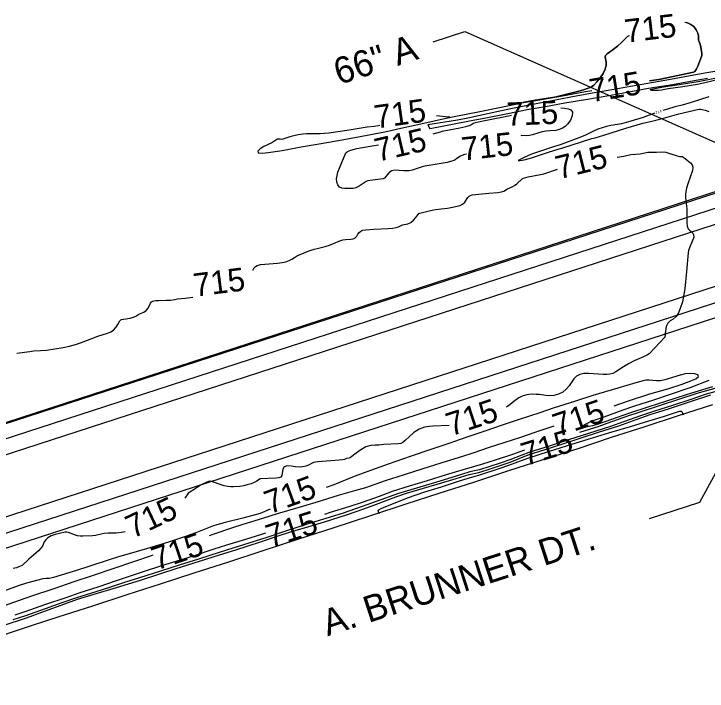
# Model space of a CAD drawing. Extents: x -468563856 to 36492962, y -306094093 to 11899197.
# Drawn here: x 1825949 to 1826935, y 532272 to 533234 of the extents above; entities that cross this region are included whole.
import ezdxf

# ---------------------------------------------------------------- set-up
doc = ezdxf.new("R2010")
doc.units = 0
for name, color, linetype in [('Default', 7, 'Continuous'), ('DT_X_Contour_Minor', 7, 'Continuous'), ('Level 14', 7, 'Continuous'), ('Level 19', 7, 'Continuous'), ('Level 40', 7, 'Continuous'), ('SC_Shading3', 7, 'Continuous')]:
    doc.layers.add(name, color=color, linetype=linetype)

msp = doc.modelspace()

# ---------------------------------------------------------------- linework, layer by layer
at = {"layer": 'Default'}
for points in [[(1824453.94, 532169.95), (1824460.14, 532150.86), (1827123.3, 533015.47), (1827116.51, 533036.4)], [(1824499.66, 532029.12), (1824505.86, 532010.03), (1827169.02, 532874.64), (1827162.83, 532893.73)]]:
    msp.add_lwpolyline(points, close=True, dxfattribs=at)
at = {"layer": 'DT_X_Contour_Minor'}
for points in [[(1826903.1, 533222.15), (1826906.83, 533221.17), (1826911.64, 533219.18), (1826916.13, 533216.02), (1826919.41, 533211.6), (1826921.48, 533206.75), (1826922.52, 533202.52), (1826922.71, 533196.91), (1826923.16, 533195.81), (1826925, 533191.26), (1826926.03, 533186.94), (1826927.42, 533177.98), (1826927.46, 533175.41), (1826926.93, 533173.37), (1826921.57, 533159.97), (1826919.29, 533155.16), (1826917.32, 533152.34), (1826915.73, 533151.15), (1826895.46, 533146.93), (1826866.38, 533141.04), (1826852.75, 533138.77)], [(1826853.39, 533138.88), (1826866.38, 533141.04), (1826895.46, 533146.93), (1826915.73, 533151.15), (1826917.32, 533152.34), (1826919.29, 533155.16), (1826921.57, 533159.97), (1826926.93, 533173.37), (1826927.46, 533175.41), (1826927.42, 533177.98), (1826926.03, 533186.94), (1826925, 533191.26), (1826923.16, 533195.81), (1826922.71, 533196.91), (1826922.52, 533202.52), (1826921.48, 533206.75), (1826919.41, 533211.6), (1826916.13, 533216.02), (1826911.64, 533219.18), (1826906.83, 533221.17), (1826905.76, 533221.45)], [(1826824.33, 533203.13), (1826822.41, 533202.38), (1826813.13, 533193.23), (1826807.34, 533188.31), (1826801.44, 533183.67), (1826792.63, 533177.31), (1826790.51, 533174.94), (1826790.15, 533172.55), (1826791.45, 533166.09), (1826791.29, 533161.37), (1826789.94, 533155.76), (1826787.15, 533149.55), (1826782.91, 533143.15), (1826778.08, 533137.3), (1826773.74, 533132.89), (1826770.68, 533130.45), (1826768.54, 533129.38), (1826764.39, 533127.84), (1826760.69, 533126.43), (1826754.57, 533124.52), (1826735.68, 533119.8), (1826718.41, 533115.95), (1826690.58, 533111.27), (1826672.73, 533108.3), (1826690.58, 533111.27), (1826718.41, 533115.95), (1826735.68, 533119.8)], [(1826735.68, 533119.8), (1826754.57, 533124.52), (1826760.69, 533126.43), (1826764.39, 533127.84), (1826768.54, 533129.38), (1826770.68, 533130.45), (1826773.74, 533132.89), (1826778.08, 533137.3), (1826782.91, 533143.15), (1826787.15, 533149.55), (1826789.94, 533155.76), (1826791.29, 533161.37), (1826791.45, 533166.09), (1826790.15, 533172.55), (1826790.51, 533174.94), (1826792.63, 533177.31), (1826801.44, 533183.67), (1826807.34, 533188.31), (1826813.13, 533193.23), (1826822.41, 533202.38), (1826823.82, 533202.93)], [(1826960.15, 533154.66), (1826931.61, 533149.8), (1826908.42, 533145.68), (1826882.92, 533141.07), (1826858.46, 533136.46), (1826825.78, 533130.78), (1826799.88, 533126.29), (1826769.03, 533120.9), (1826741.37, 533115.58), (1826711.71, 533109.98), (1826679.66, 533104.12), (1826653.42, 533098.69), (1826625.22, 533092.65), (1826594.73, 533085.88), (1826579.86, 533082.81), (1826537.94, 533076.4), (1826540.79, 533071.39), (1826543.69, 533071.78), (1826560.37, 533074.95), (1826594.67, 533081.46), (1826622.49, 533086.68), (1826649.2, 533091.89), (1826681.61, 533098.49), (1826705.17, 533102.59), (1826732.64, 533107.48), (1826764.63, 533112.92), (1826795.02, 533118.17), (1826821.29, 533122.85), (1826851.42, 533128.4), (1826885.55, 533133.96), (1826911.36, 533138.24), (1826935.28, 533142.74)], [(1826945.21, 533139.22), (1826929.93, 533135.52), (1826921.1, 533133.78), (1826900.32, 533130.53), (1826879.44, 533127.4), (1826869.92, 533125.54), (1826865.94, 533125.19), (1826860.79, 533125.12), (1826856.12, 533125.36), (1826854.07, 533125.98), (1826856.03, 533126.96), (1826865.35, 533129.08), (1826873.02, 533130.45), (1826901.3, 533134.61), (1826922.3, 533137.83), (1826945.75, 533142.86), (1826952.34, 533144.08), (1826952.43, 533143.6), (1826952.13, 533142.65), (1826951.64, 533141.97), (1826950.7, 533141.24), (1826947.63, 533139.97), (1826945.21, 533139.22)], [(1826469.85, 533075.54), (1826467.88, 533074.89), (1826461.53, 533073.92), (1826451.67, 533073), (1826426.15, 533068.67), (1826397.01, 533064.7), (1826385.02, 533063.58), (1826375.34, 533063.49), (1826365.56, 533063.49), (1826359.95, 533063.07), (1826353.68, 533062.17), (1826347.29, 533060.87), (1826341.45, 533059.33), (1826330.25, 533055.74), (1826328.09, 533055.89), (1826326.21, 533056.27), (1826324.22, 533056.1), (1826321.8, 533054.84), (1826315.94, 533050.97), (1826304.6, 533045.67), (1826299.64, 533042.37), (1826296.1, 533038.9), (1826296.44, 533036.51), (1826302.13, 533036.04), (1826310.89, 533036.91), (1826330.65, 533040.04), (1826357.78, 533044.94), (1826386.02, 533049.92), (1826416.04, 533055), (1826444.22, 533060.23), (1826476.89, 533066.48), (1826503.89, 533072.43), (1826532.02, 533078.61), (1826561.71, 533085.21), (1826577.51, 533088.55), (1826611.89, 533095.47), (1826639.79, 533101.14), (1826673.8, 533108), (1826702.32, 533112.76), (1826729.09, 533117.41), (1826762.09, 533123.71), (1826771.01, 533125.29)], [(1826937.2, 533115.99), (1826912.13, 533108.04), (1826899.48, 533104.37), (1826888.81, 533101.79), (1826878.49, 533098.72), (1826872.12, 533096.7)], [(1826860.72, 533092.97), (1826852.62, 533090.05), (1826844.07, 533086.81), (1826826.6, 533081.47), (1826813.33, 533077.9), (1826807.29, 533076.95), (1826797.9, 533075.32), (1826791.89, 533073.92), (1826785.58, 533072.14), (1826779.57, 533070.11), (1826774.5, 533068.05), (1826761.06, 533061.17), (1826752.72, 533057.81), (1826726.08, 533048.03), (1826716.28, 533045.09), (1826693.69, 533037.64), (1826685.21, 533034.52), (1826674.7, 533030.01), (1826668.94, 533027.29), (1826666.41, 533025.54), (1826669.03, 533025.5), (1826674.84, 533026.64), (1826685.1, 533029.34), (1826709.55, 533037.75), (1826724.69, 533042.49), (1826730, 533043.78), (1826743.21, 533047.98), (1826770.99, 533057.03), (1826775.68, 533058.09), (1826788.09, 533061.85), (1826819.14, 533071.81), (1826843.61, 533078.73), (1826854.39, 533081.37), (1826864.06, 533083.49), (1826878.12, 533087.36), (1826894.55, 533091.88), (1826923, 533098.55), (1826925.3, 533098.7), (1826927.95, 533098.22), (1826932.12, 533097.13), (1826937.11, 533095.56)], [(1826726.94, 533100.77), (1826732.29, 533100.24), (1826737.42, 533099.34), (1826741.38, 533097.56), (1826743.38, 533094.28), (1826742.89, 533089.16), (1826740.5, 533083.23), (1826737.05, 533077.84), (1826733.28, 533074.03), (1826729.53, 533071.62), (1826726.05, 533070.12), (1826722.93, 533069.1), (1826719.76, 533068.41), (1826711.32, 533067.68), (1826706.01, 533067.27), (1826700.6, 533066.45), (1826695.51, 533065.05), (1826686.46, 533062.04), (1826682.44, 533061.27), (1826678.64, 533061.01), (1826671.14, 533061.08), (1826669.9, 533060.97)], [(1826545.46, 533063.47), (1826555.72, 533066.47), (1826558.17, 533067.41), (1826560.5, 533067.96), (1826583.54, 533072.07), (1826591.99, 533073.88), (1826597.15, 533075.53), (1826599.87, 533076.97), (1826601.67, 533078.21), (1826603.94, 533079.28), (1826607.58, 533080.36), (1826621.46, 533083.28), (1826652.64, 533089.3), (1826656.87, 533090.17)], [(1826550.11, 533089.6), (1826567.23, 533087.59), (1826569.03, 533087.22), (1826567.23, 533087.59)], [(1826592.91, 533034.64), (1826592.55, 533034.6), (1826588.59, 533033.8), (1826584.35, 533031.94), (1826580.36, 533029.51), (1826575.37, 533025.94), (1826573.59, 533025.09), (1826565.21, 533023.01), (1826551.05, 533020.29), (1826533.68, 533017.86), (1826530.03, 533016.91), (1826519.78, 533013.23), (1826515.44, 533012.06), (1826511.12, 533011.22), (1826507.13, 533010.86), (1826503.32, 533010.95), (1826490.86, 533012.17), (1826486.74, 533011.17), (1826483.1, 533008.58), (1826480.1, 533005.24), (1826476.28, 533000.54), (1826474.54, 532999.74), (1826466.68, 532998.74), (1826456, 532997.45), (1826452.71, 532996.86), (1826450.42, 532995.99), (1826440.08, 532989.19), (1826435.73, 532987.03), (1826431.79, 532986.1), (1826424.17, 532986.15), (1826419.89, 532986.15), (1826415.67, 532986.49), (1826412.13, 532987.92), (1826409.75, 532990.93), (1826408.51, 532995.12), (1826408.24, 532999.83), (1826408.77, 533004.54), (1826409.89, 533009.07), (1826413, 533017.41), (1826421.36, 533036.79), (1826423.6, 533038.69), (1826428.55, 533040.56), (1826437.02, 533042.6), (1826455.64, 533046.14), (1826467.5, 533047.94)], [(1826806.79, 533030.64), (1826816.61, 533031.69), (1826826.57, 533034.03), (1826839.67, 533035), (1826850.59, 533037.53), (1826854.43, 533037.77), (1826862.7, 533037.74), (1826871.29, 533038.02), (1826876.23, 533037.4), (1826881.82, 533035.79), (1826892.26, 533032.13), (1826895.71, 533031.45), (1826899.69, 533031.25), (1826901.07, 533030.67), (1826903.62, 533028.52), (1826906.64, 533025.99), (1826911.33, 533022.41), (1826913.65, 533019.74), (1826914.78, 533016.13), (1826914.09, 533011.41), (1826907.48, 532992.79), (1826905.76, 532986.57), (1826904.15, 532978.25), (1826904.17, 532973.58), (1826904.53, 532968.25), (1826905.88, 532956.97), (1826906.27, 532950.11), (1826905.97, 532937.15), (1826906.38, 532932.2), (1826907.83, 532928.8), (1826909.99, 532926.51), (1826912.37, 532924.67), (1826914.47, 532922.65), (1826915.77, 532920.04), (1826915.81, 532916.48), (1826914.31, 532911.79), (1826909.83, 532901.79), (1826908.52, 532897.89), (1826907.9, 532894.44), (1826905.66, 532868.11), (1826903.38, 532843.17), (1826899.87, 532824.8), (1826896.76, 532815.5), (1826894.12, 532809.28), (1826890.66, 532803.86), (1826886.53, 532800.45), (1826882.36, 532797.95), (1826878.93, 532794.72), (1826876.8, 532789.66), (1826875.72, 532783.86), (1826874.72, 532774.76), (1826860.4, 532759.31), (1826852.35, 532751.06), (1826850.18, 532749.47), (1826844.33, 532746.86), (1826830.96, 532740.9), (1826823.19, 532736.93), (1826816.13, 532732.71), (1826804.92, 532725.41), (1826800.71, 532723.19), (1826796.81, 532721.96), (1826792.51, 532721.53), (1826787.24, 532721.68), (1826766.91, 532723.16), (1826759.86, 532722.97), (1826753.75, 532721.73), (1826749.08, 532719.11), (1826745.43, 532715.31), (1826738.75, 532705.58), (1826734.71, 532700.62), (1826729.68, 532696.45), (1826723.48, 532693.57), (1826716.81, 532691.95), (1826710.58, 532691.37), (1826705.44, 532691.61), (1826696.55, 532692.98), (1826691.65, 532693.37), (1826686.49, 532693.39), (1826681.44, 532693.06), (1826676.75, 532692.33), (1826672.17, 532690.92), (1826667.33, 532688.47), (1826662.04, 532684.86), (1826653.08, 532677.63), (1826649.87, 532675)], [(1826289.08, 532869.82), (1826290.89, 532873.32), (1826292.88, 532875.26), (1826295.16, 532876.41), (1826299.75, 532877.68), (1826306.22, 532878.59), (1826324.35, 532880.03), (1826330.56, 532880.79), (1826336.12, 532881.87), (1826340.8, 532883.37), (1826344.58, 532885.39), (1826348.24, 532887.81), (1826352.76, 532890.49), (1826358.72, 532893.25), (1826370.25, 532897.67), (1826375.26, 532899.19), (1826376.18, 532899.52), (1826380.32, 532900.65), (1826391.79, 532903.37), (1826398.25, 532905.35), (1826403.82, 532907.65), (1826412.85, 532911.76), (1826416.96, 532912.87), (1826420.94, 532913.39), (1826428.52, 532913.86), (1826431.88, 532914.47), (1826434.65, 532915.85), (1826436.7, 532918.2), (1826438.43, 532921.02), (1826440.31, 532923.6), (1826442.71, 532925.41), (1826445.34, 532926.5), (1826449.81, 532927.4), (1826460.92, 532927.91), (1826481.57, 532928.94), (1826487.76, 532929.5), (1826492.72, 532930.38), (1826496.17, 532931.64), (1826498.83, 532933.03), (1826501.66, 532934.2), (1826509.59, 532935.92), (1826513.84, 532937.73), (1826517.6, 532940.85), (1826520.67, 532944.49), (1826524.95, 532950.22), (1826526.47, 532950.67), (1826541.6, 532954.43), (1826548.8, 532955.86), (1826561.06, 532957.39), (1826565.76, 532957.95), (1826572.69, 532959.48), (1826583.69, 532961.79), (1826587.34, 532963.58), (1826590.33, 532966.54), (1826594.81, 532973.08), (1826596.69, 532975.07), (1826598.35, 532976.14), (1826600.85, 532976.93), (1826605.62, 532977.51), (1826624.5, 532979.3), (1826637.5, 532980.21), (1826642.42, 532981.03), (1826645.89, 532982.35), (1826651.04, 532985.5), (1826657.53, 532988.19), (1826661.1, 532990.1), (1826664.52, 532992.79), (1826671.73, 532999.74), (1826673.69, 533000.71), (1826680.57, 533002.45), (1826697.79, 533005.67), (1826702.63, 533007), (1826722.36, 533013.63)], [(1825953.78, 532751.82), (1825971.91, 532754.19), (1825974.53, 532754.84), (1825977.66, 532755.32), (1825987.35, 532755.71), (1825995.6, 532756.18), (1826019.2, 532760.16), (1826028.54, 532761.95), (1826036.75, 532764.07), (1826045.6, 532767.14), (1826068.86, 532775.83), (1826076.44, 532778.23), (1826081.17, 532779.64), (1826086.17, 532781.61), (1826090.77, 532784.49), (1826094.42, 532788.41), (1826097.09, 532792.59), (1826100.09, 532797.92), (1826101.5, 532799.24), (1826102.58, 532799.65), (1826105.14, 532800.2), (1826114.84, 532801.78), (1826119.49, 532802.94), (1826122.53, 532804.39), (1826126.95, 532807.47), (1826134.02, 532810.39), (1826137.51, 532812.7), (1826140.1, 532816.03), (1826143.55, 532822.82), (1826145.13, 532824.71), (1826146.66, 532825.62), (1826151.11, 532826.78), (1826155.55, 532826.91), (1826166.5, 532827.04), (1826171.82, 532827.28), (1826178.38, 532828.3), (1826181.82, 532828.94), (1826192.89, 532830.22), (1826203.73, 532831.53)], [(1826802.59, 532677.06), (1826823.25, 532684.02), (1826853.64, 532693.87), (1826878.85, 532701.42), (1826899.36, 532707.8), (1826911.88, 532712.43), (1826918.63, 532715.51), (1826922.57, 532718.53), (1826921.87, 532721.03), (1826917.46, 532722.69), (1826911, 532723.2), (1826903.87, 532722.38), (1826896.52, 532720.58), (1826874.91, 532713.86), (1826868.48, 532712.7), (1826862.7, 532712.65), (1826852.58, 532713.58), (1826847.95, 532713.31), (1826843.76, 532712.54), (1826833.78, 532709.75), (1826807.97, 532702.23), (1826772.41, 532691.56), (1826747.58, 532683.86), (1826716.13, 532673.74), (1826696.97, 532667.33), (1826667.75, 532657.5), (1826643.55, 532649.41), (1826619.12, 532641.13), (1826592.09, 532631.82), (1826567.73, 532623.58), (1826540.54, 532614.55), (1826514.28, 532605.33), (1826481.56, 532594), (1826451.03, 532583.44), (1826433.24, 532576.42), (1826404.17, 532564.82), (1826393.27, 532560.88)], [(1826942.74, 532703.97), (1826912.52, 532695.27), (1826903.76, 532692.42), (1826875.83, 532683.09), (1826852.19, 532675.43), (1826823.2, 532666.09), (1826799.17, 532657.51), (1826778.76, 532650.43), (1826771.81, 532648.52), (1826765.39, 532647.37), (1826757.15, 532646.54), (1826756.1, 532646.82), (1826756.76, 532647.67), (1826761.25, 532650.36), (1826766.65, 532653.25), (1826773.06, 532656.05), (1826788.46, 532661.63), (1826815.71, 532671.45), (1826830.54, 532676.49), (1826859.16, 532685.71), (1826882.98, 532693.53), (1826910.75, 532702.93), (1826937.89, 532713.39)], [(1826952.94, 532698.98), (1826933.72, 532693.44), (1826911.71, 532686.28), (1826885.75, 532677.68), (1826860.14, 532669.42), (1826841.44, 532663.22), (1826815.89, 532654.16), (1826797.67, 532647.85), (1826766.03, 532637.71), (1826737.86, 532628.67), (1826711.65, 532620.39), (1826681.55, 532610.61), (1826671.38, 532606.9), (1826654.34, 532600.21), (1826640.53, 532595.53), (1826611.53, 532586.23), (1826604.11, 532584.58), (1826597.33, 532583.06), (1826585.66, 532579.54), (1826559.7, 532571.41), (1826539.47, 532565.31), (1826508.88, 532556.43), (1826496.25, 532552.28), (1826464.33, 532541.04), (1826444.71, 532534.09), (1826415.85, 532524.26), (1826392.72, 532517.02), (1826367.55, 532509.11), (1826338.27, 532499.76), (1826310.19, 532490.44), (1826290.74, 532484.18), (1826268.1, 532477.15), (1826242.64, 532469.2), (1826211.96, 532459.33), (1826184.33, 532450.45), (1826157.95, 532442.22), (1826127.87, 532432.48), (1826108.09, 532426.24), (1826085.35, 532419.07), (1826065.92, 532412.85), (1826038.4, 532404.34), (1826017.36, 532396.9), (1825993.89, 532388.61), (1825966.07, 532378.76), (1825947.74, 532372.72)], [(1826753.91, 532639.67), (1826781.36, 532648.37), (1826792.89, 532652.23), (1826823.51, 532663.09), (1826835.4, 532667.14), (1826867.31, 532677.42), (1826895.88, 532686.86), (1826920.78, 532694.96), (1826949.7, 532703.33)], [(1825934.22, 532364.86), (1825967.51, 532375.95), (1825998.05, 532386.92), (1826016.7, 532393.82), (1826040.02, 532402.17), (1826063.51, 532409.21), (1826095.48, 532418.92), (1826129.5, 532429.44), (1826157.01, 532438.36), (1826180.26, 532445.73), (1826213.25, 532456.16), (1826241.65, 532465.22), (1826265.05, 532472.59), (1826298.72, 532483.28), (1826326.4, 532492.59), (1826342.62, 532497.84), (1826367.33, 532505.11), (1826390.96, 532512.3), (1826422.32, 532522.05), (1826446.95, 532530.64), (1826465.1, 532537.27), (1826492.34, 532547.77), (1826507.7, 532553.06), (1826531.69, 532559.88), (1826551.12, 532565.49), (1826577.93, 532573.93), (1826596.58, 532579.67), (1826610.31, 532582.3), (1826627.93, 532587.83), (1826655.08, 532597.07), (1826680.26, 532607.18), (1826704.56, 532615.03), (1826728.58, 532622.72), (1826755.88, 532631.55), (1826780.49, 532639.42), (1826809.57, 532648.8), (1826835.22, 532657.96), (1826854.14, 532664.63), (1826879.79, 532672.89), (1826912.62, 532683.66), (1826940.41, 532692.79)], [(1826468.91, 532523.4), (1826467.7, 532526.41), (1826467.41, 532527.94), (1826468.4, 532529.4), (1826471.72, 532531.33), (1826477.97, 532534.08), (1826498.52, 532542.22), (1826508.97, 532546.11), (1826533.57, 532554.62), (1826557.31, 532562.13), (1826580.18, 532569.48), (1826595.31, 532574.27), (1826610.12, 532578.41), (1826640.54, 532588.43), (1826652.9, 532592.69), (1826665.58, 532597.62), (1826679.99, 532602.61), (1826711, 532612.65), (1826742.36, 532622.44), (1826765.87, 532629.82), (1826796.38, 532639.19), (1826825.85, 532647.79), (1826845.67, 532653.7), (1826874.09, 532662.59), (1826891.6, 532668.02), (1826896.32, 532669.4), (1826897.73, 532669.65), (1826898.59, 532669.53), (1826899.11, 532668.87), (1826900.31, 532665.48), (1826900.88, 532664.34)], [(1826568.08, 532649.08), (1826545.11, 532648.15), (1826539.74, 532647.82), (1826532.91, 532646.65), (1826525.42, 532643.82), (1826518.06, 532638.92), (1826511.44, 532633.16), (1826506.12, 532628.14), (1826502.38, 532625.09), (1826499.27, 532623.67), (1826495.54, 532623.12), (1826475.44, 532621.87), (1826472.21, 532621.45), (1826468.4, 532621.22), (1826463.12, 532621.16), (1826456.66, 532620.57), (1826449.57, 532618.58), (1826442.45, 532614.7), (1826436, 532610.01), (1826427.78, 532603.72), (1826426.03, 532602.89), (1826422.13, 532602.31), (1826419.26, 532600.98), (1826416.36, 532600.24), (1826411.93, 532599.64), (1826399.8, 532598.68), (1826381.58, 532597.34), (1826378.01, 532596.91), (1826375.54, 532596.34), (1826373.41, 532595.44), (1826368.01, 532592.61), (1826364.37, 532591.23), (1826359.99, 532590.26), (1826354.93, 532589.87), (1826349.31, 532590.17), (1826343.35, 532591.07), (1826337.87, 532591.57), (1826333.78, 532590.46), (1826331.69, 532586.99), (1826330.23, 532578.12), (1826328.85, 532575.61), (1826326.26, 532574.52), (1826322.09, 532574.19), (1826299.84, 532573.53), (1826298.59, 532572.79), (1826294.53, 532569.9), (1826291.07, 532568.1), (1826286.46, 532566.32), (1826281.15, 532564.72), (1826275.74, 532563.43), (1826270.72, 532562.55), (1826261.81, 532561.76), (1826257.69, 532561.75), (1826253.35, 532562.19), (1826248.37, 532563.36), (1826231.69, 532569.22), (1826228.35, 532569.76), (1826226.09, 532569.4), (1826218.39, 532566.18), (1826214.56, 532564.16), (1826205.76, 532558.33), (1826199.48, 532554.3), (1826197.04, 532552.93), (1826195.71, 532550.72), (1826194.43, 532548.67), (1826192.31, 532545.9)], [(1826227.24, 532492.71), (1826232.5, 532494.57), (1826259.38, 532503.73), (1826275.33, 532508.87), (1826303.49, 532517.53), (1826324.34, 532523.91), (1826353.69, 532532.57), (1826379.09, 532540.25), (1826410.71, 532549.95), (1826434.14, 532556.6), (1826449.49, 532561.21), (1826477.64, 532570.77), (1826504.7, 532579.58), (1826529.99, 532587.61), (1826558.27, 532596.31), (1826587.78, 532605.41), (1826602.19, 532610.29), (1826625.37, 532618.31), (1826646.48, 532624.97), (1826669.86, 532632.41), (1826690.6, 532639.45), (1826717.28, 532648.54)], [(1826391.25, 532523.18), (1826399.69, 532525.84), (1826427.37, 532534.48), (1826446.54, 532540.73), (1826468.94, 532548.88), (1826487.76, 532555.63), (1826511.59, 532563.3), (1826537.2, 532571.11), (1826564.44, 532579.36), (1826590.12, 532587.21), (1826612.58, 532593.73), (1826615.87, 532594.66), (1826634.25, 532600.53), (1826658.56, 532608.41), (1826675.76, 532614.51)], [(1826313.68, 532530.28), (1826299.34, 532524.07), (1826275.05, 532517.35), (1826249.5, 532511.15), (1826237.82, 532508.15), (1826231.83, 532506.09), (1826208.07, 532496.46), (1826193.22, 532491.23), (1826169.01, 532483.46), (1826142.48, 532475.18), (1826124.85, 532469.86), (1826096.46, 532462.08), (1826084.86, 532458.41), (1826057.39, 532449.29), (1826038.27, 532443.08), (1826005.84, 532433.11), (1826002.05, 532432.05), (1825999.61, 532431.64), (1825995.1, 532431.68), (1825990.56, 532431.02), (1825983.37, 532429.31), (1825967.32, 532424.82), (1825956.65, 532421.48), (1825927.81, 532411.43)], [(1826107.71, 532498.11), (1826105.32, 532497.58), (1826098.61, 532496.47), (1826094.5, 532496.23), (1826083.19, 532496.14), (1826077.67, 532495.75), (1826073.25, 532494.84), (1826065.52, 532492.69), (1826060.9, 532492.12), (1826047.33, 532491.58), (1826043.67, 532491.67), (1826039.8, 532492.35), (1826035.37, 532493.8), (1826027.2, 532496.99), (1826024.63, 532497.61), (1826022.32, 532497.49), (1826013.99, 532495.71), (1826007.99, 532494.2), (1826002.27, 532492.18), (1825997.83, 532489.65), (1825994.68, 532486.77), (1825992.57, 532483.76), (1825989.83, 532477.76), (1825987.74, 532474.59), (1825984.34, 532471.18), (1825970.49, 532459.24), (1825961.05, 532450), (1825956.56, 532448.15), (1825952.91, 532446.91), (1825948.35, 532445.78)], [(1825951.02, 532380.03), (1825965.55, 532384.93), (1825994.58, 532394.97), (1826023.57, 532404.83), (1826042.31, 532411.04), (1826070.74, 532420.14), (1826093.72, 532428.13), (1826112.51, 532434.55), (1826135.24, 532442), (1826159.85, 532449.94), (1826186.44, 532458.03), (1826203.14, 532463.36), (1826234.17, 532473.84), (1826252.31, 532479.52), (1826279.02, 532487.75), (1826301.82, 532494.63), (1826307.73, 532496.47)], [(1825633.35, 532297.1), (1825643.73, 532300.76), (1825664.21, 532307.87), (1825689.9, 532316.37), (1825716.86, 532325.09), (1825744.71, 532333.68), (1825769.66, 532341.36), (1825799.17, 532350.72), (1825824.66, 532359.31), (1825851.14, 532368.1), (1825882.89, 532378.55), (1825891.77, 532380.98), (1825913.53, 532385.79), (1825926.08, 532389.98), (1825957.55, 532401.06), (1825976.07, 532407.39), (1826006.61, 532417.37), (1826035.14, 532427.2), (1826061.35, 532436.03), (1826091.96, 532446.5), (1826119.9, 532455.99), (1826145.12, 532464.36), (1826147.37, 532465.1)]]:
    msp.add_lwpolyline(points, dxfattribs=at)
at = {"layer": 'Level 14'}
msp.add_lwpolyline([(1826942.48, 532678.66), (1826893.93, 532662.86), (1826846.15, 532647.38), (1826798.64, 532631.9), (1826750.96, 532616.13), (1826701.17, 532600.31), (1826652.53, 532584.6), (1826604.08, 532568.59), (1826553.59, 532552.39), (1826506.81, 532537.17), (1826456.45, 532520.69), (1826404.38, 532503.88), (1826352.49, 532487.03), (1826303.17, 532471.02), (1826254.47, 532455.03), (1826205.13, 532439.16), (1826157.18, 532423.69), (1826110.15, 532408.48), (1826061.29, 532392.41), (1826011.75, 532376.55), (1825975.31, 532364.63), (1825922.34, 532347.34)], dxfattribs=at)
at = {"layer": 'Level 40'}
for p, q in [((1826545.25, 533194.52), (1826590.65, 533209.25)), ((1826590.65, 533209.25), (1827056.56, 533002.67))]:
    msp.add_line(p, q, dxfattribs=at)
msp.add_lwpolyline([(1827043.56, 532758.31), (1826923.88, 532539.43), (1826852.55, 532516.27)], dxfattribs=at)
at = {"layer": 'SC_Shading3'}
for points in [[(1824466.95, 532129.88), (1824453.94, 532169.95), (1827117.12, 533034.5), (1827130.09, 532994.55)], [(1824492.87, 532050.04), (1824505.84, 532010.09), (1827169, 532874.71), (1827156.03, 532914.66)]]:
    msp.add_lwpolyline(points, close=True, dxfattribs=at)

# ---------------------------------------------------------------- texts
at = {"layer": 'Level 19'}
for s, height, rotation, p in [('715', 33, 6.78382, (1826819.51, 533193.08)), ('715', 33, 9.27619, (1826770.34, 533108.53)), ('715', 33, 8.01568, (1826464.04, 533071.01)), ('715', 33, 2.41788, (1826650.21, 533075.01)), ('714', 4, 17.62418, (1826862.04, 533091.4)), ('715', 33, 13.09781, (1826466.54, 533023.75)), ('715', 33, 6.27389, (1826587.37, 533025.59)), ('715', 33, 14.11195, (1826724.17, 532998.74)), ('715', 33, 7.32813, (1826206.65, 532831.97)), ('715', 33, 18.35184, (1826570.49, 532633.58)), ('715', 33, 18.4607, (1826722.19, 532632.59)), ('715', 33, 17.36062, (1826676.69, 532591.16)), ('715', 33, 19.92747, (1826312.83, 532522.84)), ('715', 33, 25.35911, (1826118.25, 532487.92)), ('715', 33, 17.84191, (1826314.03, 532474.86)), ('715', 33, 18.85031, (1826152.08, 532442.79))]:
    msp.add_text(s, height=height, rotation=rotation, dxfattribs=at).set_placement(p)
at = {"layer": 'Level 40'}
for s, p in [('66" A', (1826411.48, 533132.93)), ('A. BRUNNER DT.', (1826395.18, 532349.36))]:
    msp.add_text(s, height=37.5, rotation=17.9864, dxfattribs=at).set_placement(p)

doc.saveas('drawing.dxf')
